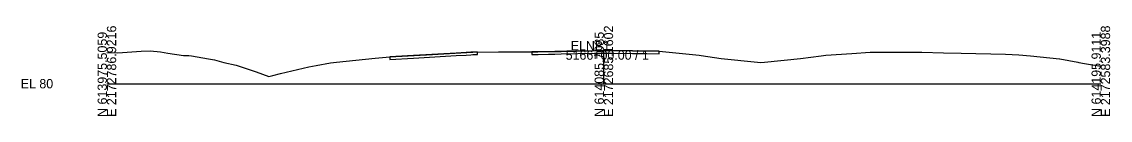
# Model space of a CAD drawing. Extents: x -26 to 1303, y -3010 to 12038.
# Drawn here: x -25.7 to 302.8, y -3009.7 to -2982.7 of the extents above; entities that cross this region are included whole.
import ezdxf

# ---------------------------------------------------------------- set-up
doc = ezdxf.new("R2010")
doc.units = 0
for name, color, linetype in [('RD_GPK_XS_Cell', 7, 'Continuous'), ('RD_XS_ExGround', 7, 'Continuous'), ('RD_XS_ExPaveRet', 7, 'Continuous')]:
    doc.layers.add(name, color=color, linetype=linetype)

msp = doc.modelspace()

# ---------------------------------------------------------------- linework, layer by layer
at = {"layer": 'RD_GPK_XS_Cell'}
for p, q in [((150, -3000), (150, -2990)), ((0, -3000), (150, -3000)), ((150, -3000), (300, -3000))]:
    msp.add_line(p, q, dxfattribs=at)
at = {"layer": 'RD_XS_ExGround'}
msp.add_lwpolyline([(0, -2990.59), (3.26, -2990.75), (10.34, -2990.25), (13.02, -2990.1), (16.14, -2990.46), (18.38, -2990.79), (23.11, -2991.51), (24.7, -2991.51), (25.55, -2991.62), (30.62, -2992.5), (32.46, -2992.79), (35.33, -2993.63), (38.99, -2994.46), (45.03, -2996.48), (48.85, -2997.8), (50.04, -2997.52), (52.42, -2996.96), (60.96, -2994.98), (63.13, -2994.5), (67.53, -2993.77), (69.3, -2993.5), (81.02, -2992.37), (85.39, -2991.95), (98.27, -2991.21), (106.84, -2990.71), (110.42, -2990.52), (118.22, -2990.47), (127.92, -2990.47), (128.45, -2990.47), (129.2, -2990.46), (130.05, -2990.44), (137.1, -2990.31), (150.9, -2990.05), (158.63, -2990.16), (166.68, -2990.27), (178.77, -2991.46), (179.34, -2991.53), (185.37, -2992.46), (196.42, -2993.57), (197.43, -2993.67), (198.49, -2993.57), (209.37, -2992.47), (215.61, -2991.62), (216.98, -2991.46), (224.88, -2990.94), (230.41, -2990.51), (234.58, -2990.52), (246, -2990.55), (252.48, -2990.68), (257.84, -2990.78), (271.2, -2991.16), (275.27, -2991.28), (278.73, -2991.62), (287.52, -2992.49), (287.54, -2992.5), (287.59, -2992.5), (293.05, -2993.5), (293.41, -2993.59), (295.08, -2993.88), (300, -2994.75)], dxfattribs=at)
at = {"layer": 'RD_XS_ExPaveRet'}
for p, q in [((92.58, -2991.54), (85.39, -2991.95)), ((92.58, -2991.54), (85.39, -2991.95)), ((85.39, -2991.95), (85.39, -2991.95)), ((85.39, -2991.95), (85.39, -2991.95)), ((85.39, -2991.95), (85.39, -2991.95)), ((85.39, -2991.95), (85.39, -2991.95)), ((85.39, -2991.95), (85.39, -2992.26)), ((85.39, -2991.95), (85.39, -2991.95)), ((85.39, -2991.95), (85.39, -2991.95)), ((85.39, -2991.95), (85.39, -2992.26)), ((85.39, -2992.26), (85.39, -2992.7)), ((85.39, -2992.26), (85.39, -2992.7)), ((85.39, -2992.7), (92.58, -2992.29)), ((85.39, -2992.7), (92.58, -2992.29)), ((85.39, -2992.7), (85.39, -2992.7)), ((85.39, -2992.7), (85.39, -2992.7)), ((85.39, -2992.7), (85.39, -2992.7)), ((85.39, -2992.7), (85.39, -2992.7)), ((85.39, -2992.7), (85.39, -2992.7)), ((85.39, -2992.7), (85.39, -2992.7)), ((85.39, -2992.7), (85.39, -2992.7)), ((105.46, -2990.79), (92.58, -2991.54)), ((105.46, -2990.79), (92.58, -2991.54)), ((92.58, -2992.29), (105.46, -2991.54)), ((92.58, -2992.29), (105.46, -2991.54)), ((108.46, -2990.63), (105.46, -2990.79)), ((108.46, -2990.63), (105.46, -2990.79)), ((105.46, -2991.54), (108.46, -2991.38)), ((105.46, -2991.54), (108.46, -2991.38)), ((109.84, -2990.55), (108.46, -2990.63)), ((109.84, -2990.55), (108.46, -2990.63)), ((108.46, -2991.38), (109.84, -2991.3)), ((108.46, -2991.38), (109.84, -2991.3)), ((110.42, -2990.52), (109.84, -2990.55)), ((110.42, -2990.52), (109.84, -2990.55)), ((109.84, -2991.3), (110.42, -2991.27)), ((109.84, -2991.3), (110.42, -2991.27)), ((111.89, -2990.51), (110.42, -2990.52)), ((111.89, -2990.51), (110.42, -2990.52)), ((128.45, -2990.47), (128.31, -2990.47)), ((128.45, -2990.47), (128.31, -2990.47)), ((130.15, -2990.44), (128.45, -2990.47)), ((130.15, -2990.44), (128.45, -2990.47)), ((128.45, -2991.22), (130.15, -2991.19)), ((128.45, -2991.22), (130.15, -2991.19)), ((133.29, -2990.38), (130.15, -2990.44)), ((133.29, -2990.38), (130.15, -2990.44)), ((130.15, -2991.19), (133.29, -2991.13)), ((130.15, -2991.19), (133.29, -2991.13)), ((135.21, -2990.35), (133.29, -2990.38)), ((135.21, -2990.35), (133.29, -2990.38)), ((133.29, -2991.13), (135.21, -2991.1)), ((133.29, -2991.13), (135.21, -2991.1)), ((137.1, -2990.31), (135.21, -2990.35)), ((137.1, -2990.31), (135.21, -2990.35)), ((135.21, -2991.1), (137.1, -2991.06)), ((135.21, -2991.1), (137.1, -2991.06)), ((147.19, -2990.12), (137.1, -2990.31)), ((147.19, -2990.12), (137.1, -2990.31)), ((137.1, -2991.06), (147.19, -2990.87)), ((137.1, -2991.06), (147.19, -2990.87)), ((150.9, -2990.05), (147.19, -2990.12)), ((150.9, -2990.05), (147.19, -2990.12)), ((147.19, -2990.87), (150.9, -2990.8)), ((147.19, -2990.87), (150.9, -2990.8)), ((152.98, -2990.08), (150.9, -2990.05)), ((152.98, -2990.08), (150.9, -2990.05)), ((150.9, -2990.8), (152.98, -2990.83)), ((150.9, -2990.8), (152.98, -2990.83)), ((158.63, -2990.16), (152.98, -2990.08)), ((158.63, -2990.16), (152.98, -2990.08)), ((152.98, -2990.83), (158.63, -2990.91)), ((152.98, -2990.83), (158.63, -2990.91)), ((163.02, -2990.22), (158.63, -2990.16)), ((163.02, -2990.22), (158.63, -2990.16)), ((158.63, -2990.91), (163.02, -2990.97)), ((158.63, -2990.91), (163.02, -2990.97)), ((166.67, -2990.27), (163.02, -2990.22)), ((166.67, -2990.27), (163.02, -2990.22)), ((163.02, -2990.97), (166.67, -2991.02)), ((163.02, -2990.97), (166.67, -2991.02)), ((166.67, -2990.58), (166.67, -2990.27)), ((166.67, -2990.58), (166.67, -2990.27)), ((166.67, -2991.02), (166.67, -2990.58)), ((166.67, -2991.02), (166.67, -2990.58))]:
    msp.add_line(p, q, dxfattribs=at)
for points in [[(85.39, -2991.95), (85.39, -2991.95)], [(110.42, -2991.27), (111.89, -2991.26), (111.89, -2990.51)], [(110.42, -2991.27), (111.89, -2991.26), (111.89, -2990.51)], [(128.31, -2990.47), (128.31, -2991.22), (128.45, -2991.22)], [(128.31, -2990.47), (128.31, -2991.22), (128.45, -2991.22)]]:
    msp.add_lwpolyline(points, dxfattribs=at)

# ---------------------------------------------------------------- texts
at = {"layer": 'RD_GPK_XS_Cell'}
for s, p in [('E 2172786.9216', (2.8, -3010)), ('E 2172685.1602', (152.8, -3010)), ('E 2172583.3988', (302.8, -3010)), ('N 613975.5059', (0, -3010)), ('N 614085.7085', (150, -3010)), ('N 614195.9111', (300, -3010))]:
    msp.add_text(s, height=2.8, rotation=90, dxfattribs=at).set_placement(p)
for s, p in [('ELNB1', (140, -2990)), ('5166+00.00 / 1', (138.48, -2992.8)), ('EL 80', (-26, -3001.4))]:
    msp.add_text(s, height=2.8, dxfattribs=at).set_placement(p)

doc.saveas('drawing.dxf')
